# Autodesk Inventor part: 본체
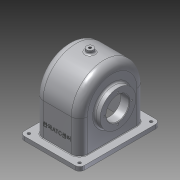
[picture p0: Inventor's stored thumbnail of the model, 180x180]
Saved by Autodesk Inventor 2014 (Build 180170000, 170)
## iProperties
Created: 2016-01
Part Number: 본체
Material: Aluminum 6061
Document SubType Name: Modeling
Designer: user
Density: 2.71 g/cm^3
Appearance: Aluminum - Flat
Mass: 812.227 g
Surface Area: 1006.17 cm^2
Volume: 299.715 cm^3
Author: user
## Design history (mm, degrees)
sketch "Sketch1"
  geometry: 1 further point
sketch "Sketch2"
  geometry: L1 (-57, 4)-(-57, -60); L2 (-57, -60)-(57, -60); L3 (57, -60)-(57, 4); A1 r 57 centre (0, 4) between (-57, 4) and (57, 4); 1 further point
  constraints: 6 end point, 2 perpendicular, 2 point on circle, 2 tangent, 1 centre point, 1 vertical, 1 vertical alignment
  dimensions: "d1" = 114 diameter of A1; "d3" = 60 distance from line of L2 point (0, 0); "d4" = 64 distance from line of L2 A1.centre
extrude "Extrusion1" new body sketch "Sketch2" stored distance "d5" = 77; taper "d6" = 0 deg
sketch "Sketch3"
  geometry: C1 r 31 at (0, 0); 1 further point
  constraints: 1 centre point, 1 coincident
  dimensions: "d7" = 62 diameter of C1
extrude "Extrusion2" join sketch "Sketch3" distance "d8" = 10; taper "d9" = 0 deg
workplane "Work Plane1"
sketch "Sketch4"
  geometry: C1 r 6 at (0, 0); 1 further point
  constraints: 1 centre point, 1 coincident
  dimensions: "d11" = 12 diameter of C1
extrude "Extrusion3" join sketch "Sketch4" stored distance "d12" = 6; taper "d13" = 0 deg
sketch "Sketch5"
  geometry: L1 (-13.5, 13)-(90.5, 13); L2 (90.5, 13)-(90.5, -127); L3 (90.5, -127)-(-13.5, -127); L4 (-13.5, -127)-(-13.5, 13); L5 (-13.5, 13)-(90.5, -127); L6 (90.5, 13)-(-13.5, -127); 1 further point
  constraints: 12 end point, 2 midpoint, 2 parallel, 1 horizontal, 1 perpendicular
  dimensions: "d14" = 104 distance of L1.start L1.end; "d15" = 140 distance of L1.end L2.end
extrude "Extrusion4" join sketch "Sketch5" distance "d16" = 7; taper "d17" = 0 deg
sketch "Sketch6"
  geometry: L1 (-57, -53)-(-57, 4) reference; L2 (57, 4)-(57, -53) reference; L3 (70, -60)-(-70, -60) reference; L4 (-51, -60)-(-51, 4); L5 (51, 4)-(51, -60); L6 (-51, -60)-(51, -60); A1 r 57 centre (0, 4) between (57, 4) and (-57, 4) reference; A2 r 51 centre (0, 4) between (51, 4) and (-51, 4); 1 further point
  constraints: 6 end point, 2 point on circle, 2 point on line, 1 centre point, 1 collinear
  dimensions: "d18" = 6 radial gap between concentric circles of A2 A1; "d19" = 6 distance between parallel lines of L4 L1; "d20" = 6 distance between parallel lines of L2 L5
extrude "Extrusion5" cut sketch "Sketch6" stored distance "d21" = 67; taper "d22" = 0 deg
sketch "Sketch7"
  geometry: C1 r 28 at (0, 0); 1 further point
  constraints: 1 centre point, 1 coincident
  dimensions: "d23" = 56 diameter of C1
extrude "Extrusion6" join sketch "Sketch7" distance "d24" = 14; taper "d25" = 0 deg
feature "FaceDraft1" dims angle "d26" = 40 deg
sketch "Sketch9"
  geometry: C1 r 20 at (0, 0); 1 further point
  constraints: 1 centre point, 1 coincident
  dimensions: "d27" = 40 diameter of C1
extrude "Extrusion7" cut sketch "Sketch9" distance "d28" = 16; taper "d29" = 0 deg
sketch "Sketch10"
  geometry: L1 (33.5, 39.747)-(19.5, 28) reference; L2 (38.5, 37.416)-(35.5, 34.899); L3 (38.5, 4)-(38.5, 61) reference; L4 (38.5, 37.416)-(38.5, 0); L5 (38.5, 0)-(35.5, 0); L6 (35.5, 0)-(35.5, 34.899); 1 further point
  constraints: 8 end point, 2 parallel, 2 point on line, 1 horizontal alignment, 1 perpendicular
  dimensions: "d30" = 5 distance between parallel lines of L2 L1; "d31" = 3 distance between parallel lines of L4 L6
revolve "Revolution1" sketch "Sketch10" stored, may be unused: angle "d32" = 90 deg
sketch "Sketch11"
  geometry: C1 r 20 at (0, 0); 1 further point
  constraints: 1 centre point, 1 coincident
  dimensions: "d33" = 40 diameter of C1
extrude "Extrusion8" cut sketch "Sketch11" distance "d34" = 15; taper "d35" = 0 deg
hole "Hole1" diameter "d38" = 4.459; stored, may be unused: countersink angle "d42" = 90 deg, drill point angle "d44" = 118 deg; dims "d36" = 10, "d37" = 10, "d39" = 6, "d40" = 4, "d41" = 2, "d43" = 8
sketch "Sketch12" dims "d45" = 56
  geometry: L1 (0, 0)-(32.111, 0); 2 further points
  constraints: 2 end point, 1 coincident, 1 horizontal, 1 horizontal alignment, 1 point on line, 2 other
hole "Hole2" sketch "Sketch12" at (28, 0) diameter "d46" = 2.459; stored, may be unused: countersink angle "d50" = 90 deg, drill point angle "d52" = 120 deg; dims "d47" = 7, "d48" = 4, "d49" = 2, "d51" = 9
pattern_circular "Circular Pattern1" dims angle "d54" = 360 deg
sketch "Sketch13" dims "d56" = 48
  geometry: L1 (0, 0)-(-29.155, 0); 2 further points
  constraints: 2 end point, 1 coincident, 1 horizontal, 1 horizontal alignment, 1 point on line, 2 other
hole "Hole3" sketch "Sketch13" at (-24, 0) diameter "d57" = 2.459; stored, may be unused: countersink angle "d61" = 90 deg, drill point angle "d63" = 120 deg; dims "d58" = 6, "d59" = 4, "d60" = 2, "d62" = 8
pattern_circular "Circular Pattern2" dims angle "d65" = 360 deg
sketch "Sketch14"
  geometry: L1 (-63.125, -34)-(140.125, -34); L2 (38.5, -23.832)-(38.5, -44.168); L3 (-13.5, -64)-(90.5, -64) reference; L4 (0, -57)-(0, 0) reference; 4 further points
  constraints: 4 end point, 2 midpoint, 1 coincident, 1 horizontal, 1 perpendicular, 1 vertical alignment, 1 other
  dimensions: "d67" = 30 distance between parallel lines of L3 L1; "d68" = 38.5 distance between parallel lines of L2 L4 (derived)
emboss "Emboss1" sketch "Sketch14" dims "d69" = 0.5, "d70" = 0
fillet "Fillet1" dims "d71" = 3
sketch "Sketch15"
  geometry: L1 (-82.5, 5)-(5.5, 5); L2 (5.5, 5)-(5.5, -119); L3 (5.5, -119)-(-82.5, -119); L4 (-82.5, -119)-(-82.5, 5); L5 (-82.5, 5)-(5.5, -119); L6 (5.5, 5)-(-82.5, -119); 5 further points
  constraints: 12 end point, 4 coincident, 2 midpoint, 2 parallel, 1 horizontal, 1 perpendicular
  dimensions: "d72" = 124 distance of L1.end L2.end; "d73" = 44 distance from line of point (-38.5, -57) L2
hole "Hole4" sketch "Sketch15" at (-82.5, -119), (5.5, -119), (5.5, 5), (-82.5, 5) diameter "d74" = 5; stored, may be unused: countersink angle "d78" = 90 deg, drill point angle "d80" = 0 deg; dims "d75" = 6, "d76" = 4, "d77" = 2, "d79" = 8
fillet "Fillet2" dims "d81" = 8
fillet "Fillet3" dims "d82" = 14
fillet "Fillet4" dims "d83" = 9
fillet "Fillet5" dims "d84" = 3
fillet "Fillet6" dims "d85" = 1
fillet "Fillet7" dims "d86" = 3
chamfer "Chamfer1" distance "d87" = 1; stored, may be unused: second distance "d88" = 2, angle "d89" = 45 deg
body "Solid1"
other parameters: "d10" = 67
